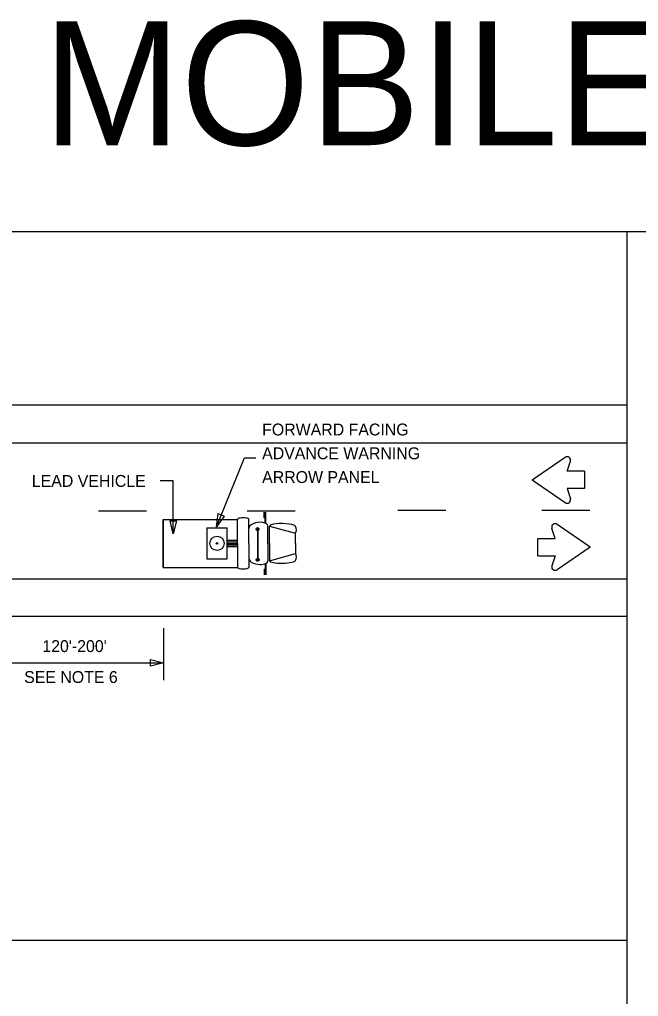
# Model space of a CAD drawing. Extents: x 1807779 to 1818251, y 673292 to 678849.
# Drawn here: x 1817093.8 to 1817406.5, y 677044 to 677537 of the extents above; entities that cross this region are included whole.
import ezdxf

# ---------------------------------------------------------------- set-up
doc = ezdxf.new("R2010")
doc.units = 0
for name, color, linetype in [('DSN_DRFT_Guideline-No-Plot', 7, 'Continuous'), ('DSN_RDWY_Drive', 7, 'Continuous'), ('R_No Plot', 7, 'Continuous')]:
    doc.layers.add(name, color=color, linetype=linetype)

msp = doc.modelspace()

# ---------------------------------------------------------------- linework, layer by layer
at = {"layer": 'DSN_DRFT_Guideline-No-Plot'}
msp.add_lwpolyline([(1816600.63, 676379.88), (1818250.63, 676379.88), (1818250.63, 677429.88), (1816600.63, 677429.88)], close=True, dxfattribs=at)
at = {"layer": 'DSN_RDWY_Drive'}
for p, q in [((1817400.69, 677429.88), (1817400.69, 676379.88)), ((1816600.9, 677342.61), (1817400.65, 677342.61)), ((1816600.9, 677323.48), (1817400.65, 677323.48)), ((1817352.79, 677304.65), (1817369.46, 677316.09)), ((1817370.51, 677309.02), (1817372.14, 677314.09)), ((1817379.18, 677309.02), (1817370.51, 677309.02)), ((1817379.18, 677309.02), (1817379.18, 677300.29)), ((1817352.79, 677304.65), (1817369.46, 677293.22)), ((1817379.18, 677300.29), (1817370.51, 677300.29)), ((1817370.51, 677300.29), (1817372.14, 677295.21)), ((1817217.46, 677285.51), (1817217.46, 677288.47)), ((1817217.93, 677282.65), (1817217.93, 677288.47)), ((1817218.32, 677282.65), (1817218.32, 677288.47)), ((1817166.4, 677284.78), (1817203.95, 677284.78)), ((1817166.4, 677260.52), (1817166.4, 677284.78)), ((1817166.4, 677284.78), (1817166.4, 677260.53)), ((1817203.95, 677272.65), (1817203.95, 677284.78)), ((1817209.7, 677272.65), (1817209.7, 677284.78)), ((1817219.34, 677272.65), (1817219.34, 677281.39)), ((1817220.14, 677281.39), (1817233.27, 677277.8)), ((1817220.14, 677272.65), (1817220.14, 677281.39)), ((1817382.08, 677270.79), (1817365.41, 677282.23)), ((1817188.46, 677280.42), (1817198.72, 677280.42)), ((1817188.46, 677280.42), (1817188.46, 677264.89)), ((1817198.72, 677264.89), (1817198.72, 677280.42)), ((1817213.37, 677280.03), (1817213.37, 677280.03)), ((1817213.99, 677279.68), (1817213.99, 677264.62)), ((1817214.03, 677279.68), (1817214.03, 677264.62)), ((1817214.07, 677279.68), (1817214.07, 677264.62)), ((1817214.15, 677279.68), (1817214.15, 677264.62)), ((1817214.25, 677280.53), (1817214.25, 677280.53)), ((1817214.27, 677279.68), (1817214.27, 677264.62)), ((1817233.27, 677272.65), (1817233.27, 677277.8)), ((1817364.36, 677275.16), (1817362.73, 677280.23)), ((1817198.72, 677274.21), (1817203.95, 677274.21)), ((1817198.72, 677273.43), (1817203.95, 677273.43)), ((1817198.72, 677272.65), (1817203.95, 677272.65)), ((1817198.72, 677271.88), (1817203.95, 677271.88)), ((1817198.72, 677271.1), (1817203.95, 677271.1)), ((1817203.95, 677272.65), (1817203.95, 677260.53)), ((1817209.7, 677272.65), (1817209.7, 677260.53)), ((1817219.34, 677272.65), (1817219.34, 677263.92)), ((1817220.14, 677272.65), (1817220.14, 677263.92)), ((1817233.27, 677272.65), (1817233.27, 677267.51)), ((1817355.68, 677266.43), (1817355.68, 677275.16)), ((1817355.68, 677275.16), (1817364.36, 677275.16)), ((1817220.14, 677263.92), (1817233.27, 677267.51)), ((1817355.68, 677266.43), (1817364.36, 677266.43)), ((1817364.36, 677266.43), (1817362.73, 677261.36)), ((1817382.08, 677270.79), (1817365.41, 677259.36)), ((1817188.46, 677264.89), (1817198.72, 677264.89)), ((1817213.41, 677264.49), (1817213.41, 677264.49)), ((1817214.29, 677265), (1817214.29, 677265)), ((1817217.93, 677262.66), (1817217.93, 677256.83)), ((1817218.32, 677262.66), (1817218.32, 677256.83)), ((1817166.4, 677260.53), (1817203.95, 677260.53)), ((1817217.46, 677259.8), (1817217.46, 677256.83)), ((1816600.9, 677254.79), (1817400.65, 677254.79)), ((1816600.9, 677235.91), (1817400.65, 677235.91)), ((1817166.56, 677229.85), (1817166.56, 677203.67)), ((1817083.27, 677212.38), (1817166.56, 677212.38)), ((1816600.9, 677072.4), (1817400.95, 677072.4))]:
    msp.add_line(p, q, dxfattribs=at)
for points in [[(1817193.28, 677281.04), (1817207.42, 677315.82), (1817213.2, 677315.82)], [(1817171.48, 677277.49), (1817171.48, 677304.18), (1817164.86, 677304.18)], [(1817133.65, 677289.03), (1817157.91, 677289.03)], [(1817208.79, 677289.03), (1817233.04, 677289.03)], [(1817284.94, 677289.36), (1817309.2, 677289.36)], [(1817357.7, 677289.36), (1817381.95, 677289.36)], [(1817213.35, 677279.76), (1817213.61, 677279.31)], [(1817213.37, 677280.03), (1817213.85, 677279.18)], [(1817213.43, 677280.21), (1817214.04, 677279.14)], [(1817213.52, 677280.34), (1817214.2, 677279.16)], [(1817213.63, 677280.44), (1817214.35, 677279.2)], [(1817213.75, 677280.53), (1817214.47, 677279.27)], [(1817213.89, 677280.57), (1817214.58, 677279.37)], [(1817214.04, 677280.6), (1817214.68, 677279.49)], [(1817214.23, 677280.58), (1817214.75, 677279.66)], [(1817214.44, 677280.5), (1817214.79, 677279.89)], [(1817213.39, 677264.23), (1817213.66, 677263.77)], [(1817213.41, 677264.49), (1817213.9, 677263.65)], [(1817213.47, 677264.68), (1817214.08, 677263.61)], [(1817213.56, 677264.81), (1817214.24, 677263.63)], [(1817213.67, 677264.91), (1817214.39, 677263.67)], [(1817213.79, 677264.99), (1817214.52, 677263.74)], [(1817213.93, 677265.03), (1817214.63, 677263.83)], [(1817214.08, 677265.07), (1817214.72, 677263.96)], [(1817214.27, 677265.05), (1817214.8, 677264.12)], [(1817214.48, 677264.97), (1817214.83, 677264.35)]]:
    msp.add_lwpolyline(points, dxfattribs=at)
for points in [[(1817197.24, 677286.45), (1817193.28, 677281.04), (1817194.23, 677287.67)], [(1817173.1, 677283.99), (1817171.48, 677277.49), (1817169.85, 677283.99)], [(1817160.06, 677214.01), (1817166.56, 677212.38), (1817160.06, 677210.76)]]:
    msp.add_lwpolyline(points, close=True, dxfattribs=at)
for centre, radius in [((1817193.59, 677272.65), 3.62), ((1817214.06, 677279.87), 0.728), ((1817193.59, 677272.65), 0.451), ((1817214.11, 677264.34), 0.728)]:
    msp.add_circle(centre, radius, dxfattribs=at)
for centre, radius, start, end in [((1817370.45, 677314.63), 1.77, 342.1824, 124.4455), ((1817370.45, 677294.67), 1.77, 235.5545, 17.8176), ((1817230.05, 677279.52), 3.64, 331.8801, 28.1199), ((1817364.41, 677280.77), 1.77, 55.5545, 197.8176), ((1817230.05, 677265.79), 3.64, 331.8801, 28.1199), ((1817364.41, 677260.82), 1.77, 162.1824, 304.4455)]:
    msp.add_arc(centre, radius, start, end, dxfattribs=at)
for centre, major_axis, ratio, start_param, end_param in [((1817206.82, 677284.78), (2.88, 0), 0.269913, 0, 3.141593), ((1817214.52, 677280.79), (4.82, 0.6), 0.503092, 0, 3.141593), ((1817226.7, 677281.31), (6.56, -0.08), 0.2034, 0, 3.141593), ((1817214.52, 677264.52), (4.82, -0.6), 0.503092, 3.141593, 6.283185), ((1817226.7, 677263.99), (6.56, 0.08), 0.2034, 3.141593, 6.283185), ((1817206.82, 677260.53), (2.88, 0), 0.269913, 3.141593, 6.283185)]:
    msp.add_ellipse(centre, major_axis=major_axis, ratio=ratio, start_param=start_param, end_param=end_param, dxfattribs=at)

# ---------------------------------------------------------------- texts
for s, p in [('FORWARD FACING', (1817216.39, 677327.12)), ('ADVANCE WARNING ', (1817216.39, 677315.12)), ('LEAD VEHICLE', (1817100.05, 677301.18)), ('ARROW PANEL', (1817216.39, 677303.12)), ("120'-200'", (1817105.36, 677217.8)), ('SEE NOTE 6', (1817096.17, 677202.19))]:
    msp.add_text(s, height=6, dxfattribs=at).set_placement(p)
at = {"layer": 'R_No Plot'}
msp.add_text('MOBILE WZ', height=62.502, dxfattribs=at).set_placement((1817105.74, 677473.61))

doc.saveas('drawing.dxf')
